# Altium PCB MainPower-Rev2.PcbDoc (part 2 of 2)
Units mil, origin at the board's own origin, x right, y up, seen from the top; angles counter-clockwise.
Board outline 7780 x 7780 mil, 4 copper layers (Top Layer, Internal Plane 1, Internal Plane 2, Bottom Layer); 128 components, 89 nets, 523 pads, 30 vias.
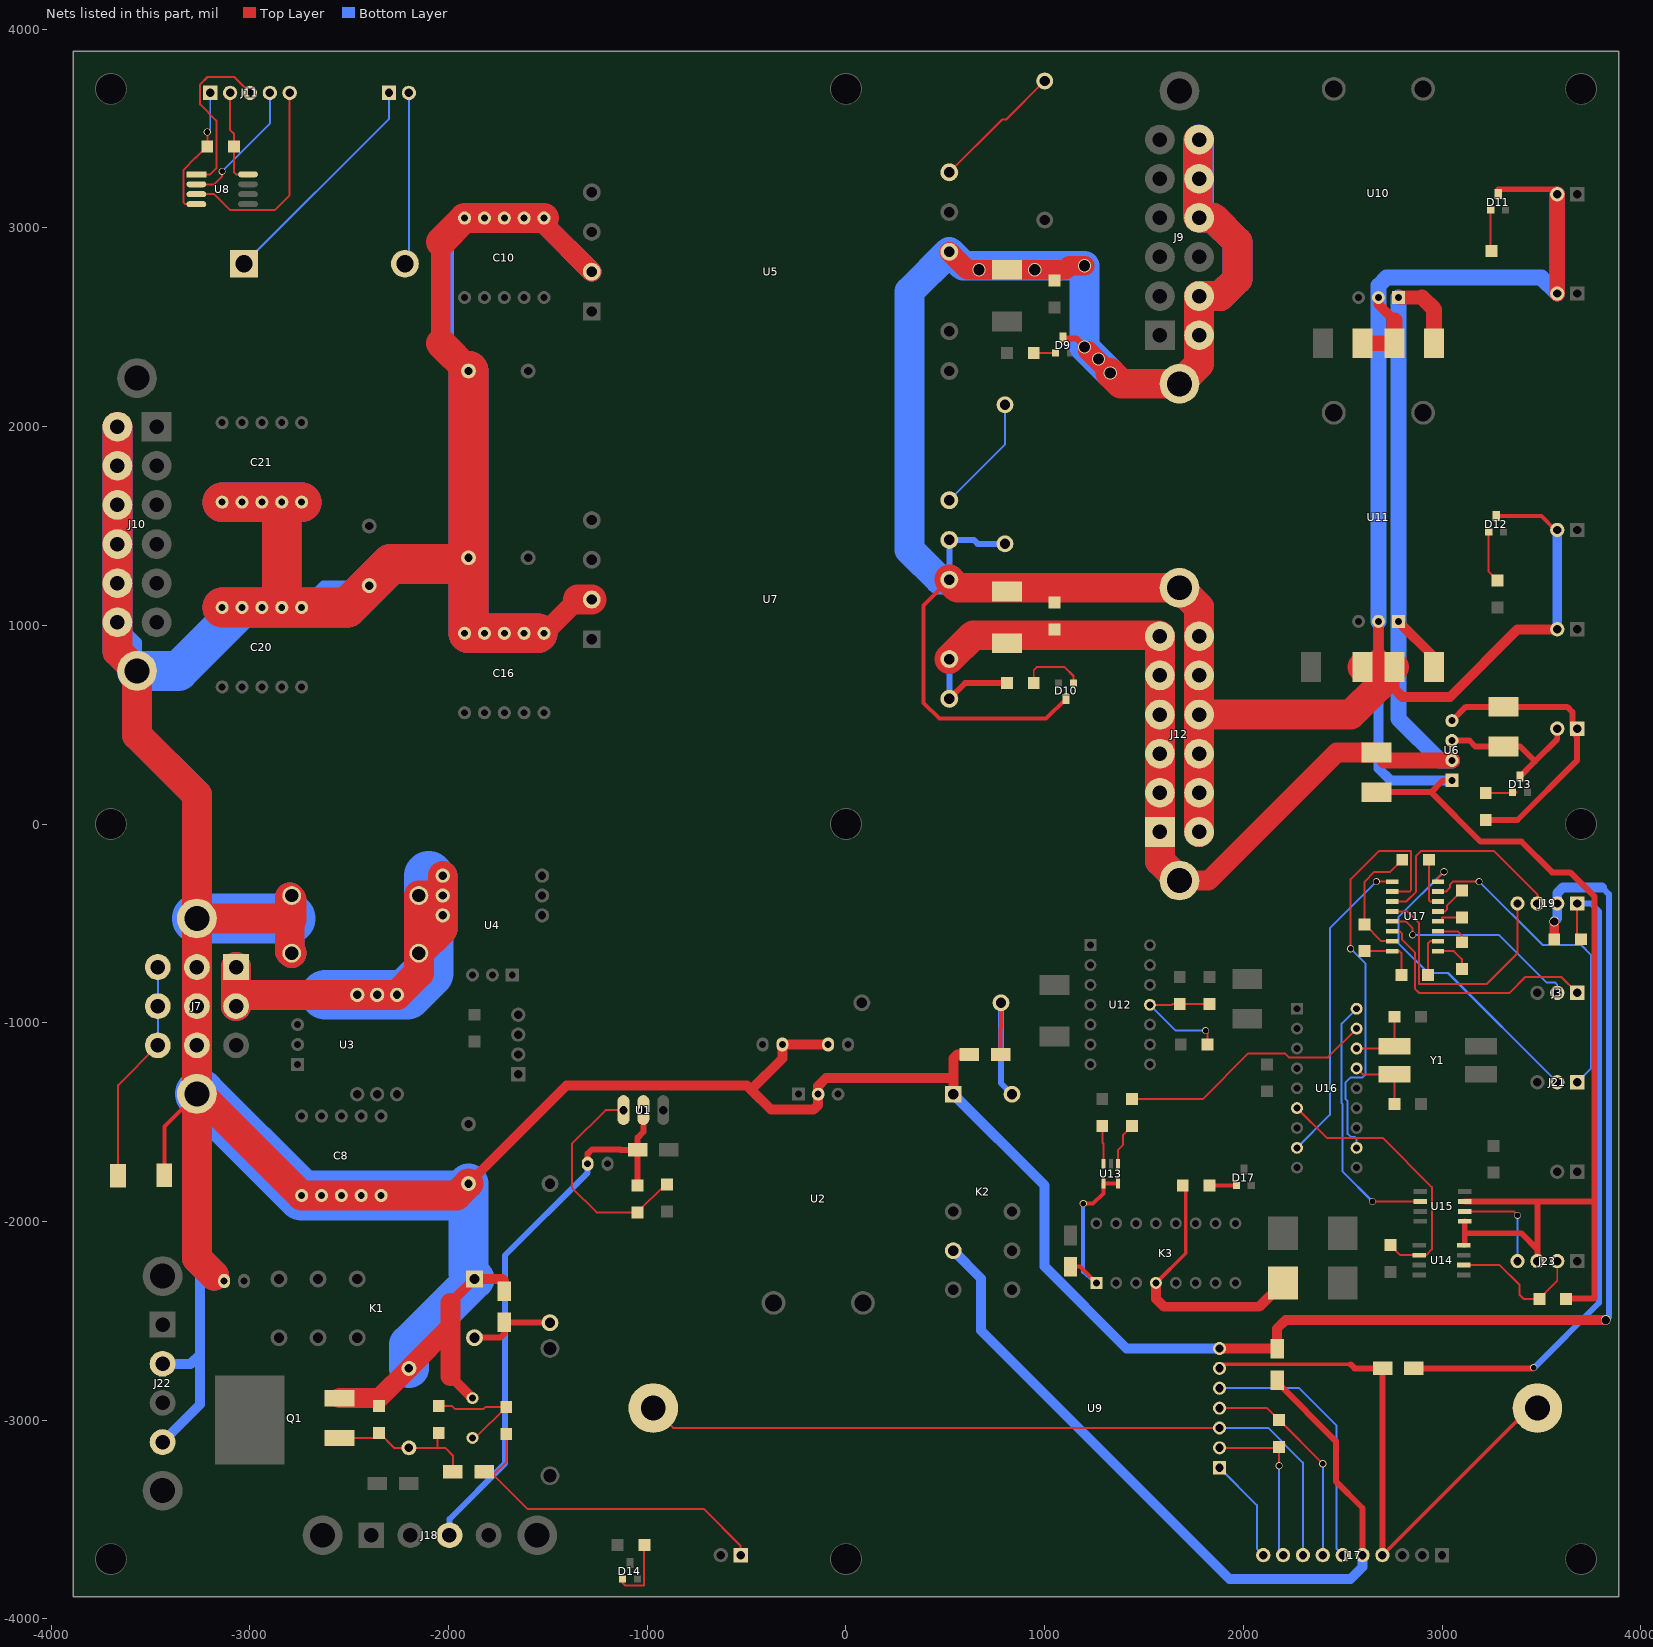
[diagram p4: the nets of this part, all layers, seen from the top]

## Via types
v1: diameter 36, hole 28, Top Layer to Bottom Layer, 15 vias
v2: diameter 50, hole 42, Top Layer to Bottom Layer, 9 vias
v3: diameter 66, hole 56, Top Layer to Bottom Layer, 6 vias

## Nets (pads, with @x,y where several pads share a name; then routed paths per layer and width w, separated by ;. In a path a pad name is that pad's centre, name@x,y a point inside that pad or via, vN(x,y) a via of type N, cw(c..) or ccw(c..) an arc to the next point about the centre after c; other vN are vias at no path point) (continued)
MVC12V+: C13.1 C17.1 C18.1 C22.1 C24.1 J12.0@1678.5,-284.5 J12.1 J12.2 J12.3 J12.4 J12.5 J12.6 R10.1 U6.2 U7.5 U7.6 U10.1 U11.1 | length 11136.6
  Top Layer w30: U7.5@520,630 600,710 R10.1@810,710
  Top Layer w50: U7.6@520,830 520,890 540,910 C18.1@810,910 937,910 1007,980 C17.1@1050,980 1545,980 J12.6@1580,945 ; C13.1@2670,360 C13.1@2710,320 ; U11.1@2780,1020 2960,840 C24.1@2960,790
  Top Layer w70: U10.1@2780,2650 2900,2650
  Top Layer w80: C13.1@2710,320 U6.2@3050,320 ; 2900,2650 2960,2590 C22.1@2960,2420
  Top Layer w100: J12.0@1678.5,-284.5 1825.5,-284.5 2470,360 C13.1@2670,360
  Top Layer w150: U7.6@520,830 640,950 J12.6@1575,950 ; J12.6@1580,945 1580,-186 J12.0@1678.5,-284.5
  Bottom Layer w30: U7.5@520,630 U7.6@520,830
  Bottom Layer w50: J12.1@1580,-40 J12.2@1580,157 J12.3@1580,354 J12.4@1580,551 J12.5@1580,748 J12.6@1580,945
  Bottom Layer w80: U10.1@2780,2650 U11.1@2780,1020 2780,530 2990,320 U6.2@3050,320
  Bottom Layer w150: J12.6@1580,945 1580,-186 J12.0@1678.5,-284.5
MVCGND: C11.2 C12.2 C13.2 C17.2 C18.2 C22.2 C23.2 C24.2 C25.2 D9.3 D10.3 D11.3 D12.3 J9.0@1678.5,2215.5 J9.7 J9.8 J9.10 J9.11 J9.12 J12.0@1678.5,1189.5 J12.7 J12.8 J12.9 J12.10 J12.11 J12.12 J13.2 J14.2 J15.2 J16.2 J23.3 R7.2 R19.2 U5.7 U6.1 U7.7 U7.8 U10.2 U11.2 U14.4 U15.5 U15.7 | length 29352.8
  Top Layer w20: U7.7@520,1230 390,1100 390,610 470,530 1007,530 D10.3@1107,630 ; D12.3@3273,1550 3500,1550 3570,1480 J15.2@3580,1480
  Top Layer w30: 995,2790 C11.2@1050,2735 ; D9.3@1093,2450 1093,2443 1161,2443 v3@1337,2257 ; C13.2@2670,160 2945,160 ; U6.1@3050,220 3005,220 2945,160 ; U14.4@3110,-2120 3114.41,-2120 U15.5@3114.41,-2000 ; 3114.41,-2060 3190,-2060 3400,-2060 3480,-2140 J23.3@3480,-2200 3480,-1900 ; U15.7@3114.41,-1900 3480,-1900 ; D11.3@3283,3170 3283,3195 3580,3195 J13.2@3580,3170 ; R19.2@3625,-2390 3627,-2388 3768,-2388 3768,-1900 ; 2945,160 3194,-89 3400,-89 3554,-243 3645,-243 3768,-366 3768,-1900 ; 3480,-1900 3768,-1900
  Top Layer w50: U7.7@520,1230 580,1170 C18.2@810,1170 995,1170 C17.2@1050,1115 ; C11.2@1050,2735 1125,2810 ; C25.2@2600,790 2680,870 ; U11.2@2680,1020 2680,870 ; U10.2@2680,2650 2680,2615 2760,2535 ; J16.2@3580,980 3380,980 3040,640 2800,640 2760,680 C24.2@2760,790 2680,870
  Top Layer w80: C23.2@2600,2420 C22.2@2760,2420 2760,2535 ; J14.2@3580,2670 J13.2@3580,3170
  Top Layer w100: U5.7@520,2880 610,2790 C12.2@810,2790 995,2790 1105,2790 1125,2810 v3(1200,2810) ; v3@1218,2382 v3(1330,2270)
  Top Layer w150: U7.7@520,1230 560.5,1189.5 J12.0@1678.5,1189.5 1777,1091 J12.7@1777,-40 ; v3(1330,2270) 1384.5,2215.5 J9.0@1678.5,2215.5 1777,2314 J9.7@1777,2460 ; J9.12@1770,3440 J9.10@1770,3058 ; J12.10@1777,551 2541,551 2680,690 2680,790 ; C25.2@2600,790 C24.2@2760,790 ; J9.10@1770,3058 J9.10@1777,3051 ; J9.10@1770,3058 J9.10@1777,3051 ; J9.7@1777,2460 J9.8@1777,2657 ; J9.7@1777,2460 J9.8@1777,2657 ; J9.8@1777,2657 1884,2657 1970,2743 1970,2930 1849,3051 J9.10@1777,3051
  Bottom Layer w30: U7.7@520,1230 U7.8@520,1430 643,1430 663,1410 R7.2@800,1410
  Bottom Layer w50: J12.7@1777,-40 J12.8@1777,157 J12.9@1777,354 J12.10@1777,551 J12.11@1777,748 J12.12@1777,945 ; U11.2@2680,1020 2680,280 2740,220 U6.1@3050,220 ; J16.2@3580,980 J15.2@3580,1480
  Bottom Layer w80: U11.2@2680,1020 U10.2@2680,2650 2680,2710 2720,2750 3500,2750 J14.2@3580,2670 J13.2@3580,3170
  Bottom Layer w150: U7.7@520,1230 470,1230 320,1380 320,2680 U5.7@520,2880 590,2810 v3(1200,2810) v3(1200,2400) v3(1330,2270) ; J12.0@1678.5,1189.5 1777,1091 1777,930 J12.7@1777,-40 ; J9.7@1777,2460 J9.8@1777,2657 1884,2657 1970,2743 1970,2930 1849,3051 J9.10@1777,3051 J9.11@1777,3248 J9.12@1777,3445
  other v3: 1270,2340 670,2790 950,2790
NetB1_1: B1.1 J20.1 | length 1162.4
  Bottom Layer w10: B1.1@-3030,2820 -2300,3550 J20.1@-2300,3680
NetB1_2: B1.2 J20.2 | length 868.3
  Bottom Layer w10: B1.2@-2220,2820 -2200,2840 J20.2@-2200,3680
NetC5_1: C5.1 R3.2 R4.1 | length 585.1
  Top Layer w10: R4.1@-2050,-2930 -1982,-2930 -1966.39,-2945.61 -1825.61,-2945.61 -1815,-2935 -1795,-2935 R3.2@-1710,-2935 -1865,-3090 C5.1@-1880,-3090
NetC26_2: C26.2 R15.2 R16.1 U12.11 | length 710.1
  Top Layer w10: U12.11@1530,-910 1640,-910 1645,-905 C26.2@1680,-905 R15.2@1830,-905 ; v1(1810,-1040) 1820,-1050 R16.1@1820,-1110
  Bottom Layer w10: U12.11@1530,-910 1660,-1040 v1(1810,-1040)
NetC30_1: C30.1 U16.16 Y1.4 | length 350
  Top Layer w10: U16.16@2570,-1130 2721,-1130 2721,-1118.27 Y1.4@2760,-1118.27 C30.1@2760,-970
NetC31_1: C31.1 U16.15 Y1.1 | length 352.4
  Top Layer w10: U16.15@2570,-1230 2600,-1260 Y1.1@2760,-1260 C31.1@2760,-1410
NetC33_1: C33.1 C34.2 U17.16 | length 299.1
  Top Layer w10: C33.1@2610,-640 U17.16@2749.69,-640 2785,-640 2795,-650 C34.2@2795,-760
NetC33_2: C33.2 C36.1 U17.15 | length 624.9
  Top Layer w10: U17.15@2749.69,-590 2695,-590 C33.2@2610,-505 2610,-291 2660,-241 2739,-241 C36.1@2800,-180
NetC34_1: C34.1 U17.2 | length 214.1
  Top Layer w10: C34.1@2930,-760 2930,-600 2940,-590 U17.2@2980,-590
NetC35_1: C35.1 U17.1 | length 186.6
  Top Layer w10: U17.1@2980,-640 3060,-640 3100,-680 C35.1@3100,-730
NetC35_2: C35.2 U17.3 | length 163.3
  Top Layer w10: U17.3@2980,-540 3080,-540 3100,-560 C35.2@3100,-595
NetC36_2: C36.2 U17.6 | length 252.1
  Top Layer w10: C36.2@2935,-180 2935,-213 2934.29,-213.71 2934.29,-383.29 2941,-390 U17.6@2980,-390
NetC37_1: C37.1 U17.4 | length 140
  Top Layer w10: U17.4@2980,-490 2999,-490 2999,-470 C37.1@3100,-470
NetC37_2: C37.2 U17.5 | length 175.8
  Top Layer w10: U17.5@2980,-440 3016,-440 3026,-430 3026,-409 C37.2@3100,-335
NetC38_1: C38.1 J11.2 U8.8 | length 482.4
  Top Layer w10: J11.2@-3100,3680 -3100,3493 -3080,3473 C38.1@-3080,3410 -3080,3280 -3070,3270 U8.8@-3010,3270
NetC38_2: C38.2 J11.1 U8.4 | length 676.7
  Top Layer w10: U8.4@-3270,3120 -3325,3120 -3335.61,3130.61 -3335.61,3291.39 -3272,3355 -3270,3355 C38.2@-3215,3410 v1(-3215,3483)
  Bottom Layer w10: v1(-3215,3483) -3200,3498 J11.1@-3200,3680
NetD1_2: D1.2 K1.8 R1.1 | length 444.8
  Top Layer w10: -1720,-2565.28 -1720,-2510 D1.2@-1720,-2508.74
  Top Layer w30: K1.8@-1870,-2585.28 -1740,-2585.28 -1720,-2565.28 ; D1.2@-1720,-2510 R1.1@-1490,-2510
NetD3_2: D3.2 K2.8 R2.1 | length 743.4
  Top Layer w10: 778.74,-1030.26 780,-1029
  Top Layer w20: D3.2@778.74,-1160 778.74,-1030.26 ; 780,-1029 R2.1@780,-900
  Bottom Layer w30: R2.1@780,-900 780,-1304.72 K2.8@835.28,-1360
NetD5_2: D5.2 J4.1 R3.1 | length 1725.4
  Top Layer w10: D5.2@-1821.26,-3260 -1791,-3260 D5.2@-1774.5,-3276.5 ; R3.1@-1710,-3070 -1710,-3212 D5.2@-1774.5,-3276.5 ; J4.1@-530,-3680 -530,-3634 -717,-3447 -1604,-3447 D5.2@-1774.5,-3276.5
NetD9_2: D9.2 R8.2 | length 110
  Top Layer w10: R8.2@945,2370 D9.2@1055,2370
NetD10_2: D10.2 R10.2 | length 324.9
  Top Layer w10: R10.2@945,710 945,775 960,790 1100,790 1145,745 D10.2@1145,710
NetD11_2: D11.2 R12.2 | length 212.1
  Top Layer w10: R12.2@3250,2885 3245,2890 D11.2@3245,3090 D11.2@3250,3090
NetD12_2: D12.2 R9.2 | length 263.6
  Top Layer w10: D12.2@3235,1470 3235,1270 R9.2@3280,1225
NetD13_2: D13.2 R14.2 | length 179.1
  Top Layer w10: R14.2@3220,155 3355,155 3371,155 3376,160 D13.2@3355,160
NetD14_2: D14.2 R11.2 | length 337.8
  Top Layer w10: D14.2@-1125,-3800 -1125,-3820 -1112,-3833 -1016,-3833 -1016,-3631 R11.2@-1015,-3630
NetD15_1: D15.1 K3.1 U13.1 U13.2 | length 841.4
  Top Layer w10: D15.1@1130,-2228.74 D15.1@1130,-2228
  Top Layer w20: D15.1@1130,-2228 1178,-2228 K3.1@1260,-2310 ; v1(1194,-1911) 1244,-1911 1295,-1860 U13.2@1295,-1810 U13.1@1370,-1810
  Bottom Layer w20: v1(1194,-1911) 1194,-2254 K3.1@1260,-2310
NetD17_2: D17.2 R22.1 | length 135
  Top Layer w20: R22.1@1830,-1820 D17.2@1965,-1820
NetD19_1: D19.1 J17.4 U9.00 U9.6 | length 2864.9
  Top Layer w18: U9.6@1880,-2740 1900,-2720 2540,-2720 ; J17.4@2700,-3680 3440,-2940 U9.00@3480,-2940 ; D19.1@2700,-2741.26 D19.1@2701.26,-2740
  Top Layer w30: 2540,-2720 2560,-2740 D19.1@2701.26,-2740 ; J17.4@2700,-3680 D19.1@2700,-2741.26
NetF1_1: F1.1 K3.4 R22.2 | length 1399.6
  Top Layer w10: F1.1@2200,-2365 F1.1@2200,-2310
  Top Layer w18: K3.4@1560,-2310 1710,-2160 1710,-1835 R22.2@1695,-1820
  Top Layer w50: K3.4@1560,-2310 1560,-2390 1600,-2430 2080,-2430 F1.1@2200,-2310
NetJ3_1: J3.1 U17.14 | length 1250.4
  Top Layer w10: U17.14@2749.69,-540 2788,-540 2798,-550 2798,-581 2863,-646 2863,-829 2884,-850 3340,-850 3420,-770 3600,-770 J3.1@3680,-850
NetJ3_2: J3.2 U17.13 | length 1023.4
  Top Layer w10: U17.13@2749.69,-490 2818,-490 2852,-524 v1(2852,-558)
  Bottom Layer w10: v1(2852,-558) 3286,-558 3527,-799 3570,-799 3580,-809 J3.2@3580,-850
NetJ5_1: 
NetJ5_2: 
NetJ11_3: J11.3 U8.1 | length 869
  Top Layer w10: U8.1@-3270,3270 -3200,3270 -3169.59,3300.41 -3169.59,3540.59 -3251.34,3622.34 -3251.34,3722.52 -3213.86,3760 -3080,3760 J11.3@-3000,3680
NetJ11_4: J11.4 U8.2 | length 666
  Top Layer w10: U8.2@-3270,3220 -3180,3220 -3140,3260 v1(-3140,3285)
  Bottom Layer w10: v1(-3140,3285) -2900,3525 J11.4@-2900,3680
NetJ11_5: J11.5 U8.3 | length 1050
  Top Layer w10: U8.3@-3270,3170 -3180,3170 -3099.75,3089.75 -2874.25,3089.75 -2800,3164 J11.5@-2800,3680
NetJ17_6: J17.6 U9.5 | length 1331.7
  Bottom Layer w10: U9.5@1880,-2840 2281,-2840 2469,-3028 2469,-3649 J17.6@2500,-3680
NetJ17_7: J17.7 R13.1 U9.4 | length 1096
  Top Layer w10: U9.4@1880,-2940 2120,-2940 R13.1@2180,-3000 v1(2400,-3220)
  Bottom Layer w10: J17.7@2400,-3680 v1(2400,-3220)
NetJ17_8: J17.8 U9.0 U9.3 | length 3848.9
  Top Layer w10: U9.0@-970,-2940 -870,-3040 U9.3@1880,-3040
  Bottom Layer w10: U9.3@1880,-3040 2125,-3040 2300,-3215 J17.8@2300,-3680
NetJ17_9: J17.9 R13.2 U9.2 | length 855.4
  Top Layer w10: U9.2@1880,-3140 2175,-3140 R13.2@2180,-3135 v1(2180,-3230)
  Bottom Layer w10: v1(2180,-3230) 2180,-3660 J17.9@2200,-3680
NetJ17_10: J17.10 U9.1 | length 531.1
  Bottom Layer w10: U9.1@1880,-3240 2068,-3428 2068,-3648 J17.10@2100,-3680
NetJ21_1: J21.1 U17.7 | length 1623.2
  Top Layer w10: U17.7@2980,-340 3020,-340 3040,-320 3040,-305 3055,-290 v1(3187,-290)
  Bottom Layer w10: v1(3187,-290) 3506,-609 3700,-609 3751,-660 3751,-1229 J21.1@3680,-1300
NetJ21_2: J21.2 U17.8 | length 1607.6
  Top Layer w10: U17.8@2980,-290 2980,-270 v1(3010,-240)
  Bottom Layer w10: v1(3010,-240) 2780,-470 2780,-600 2930,-750 3030,-750 J21.2@3580,-1300
NetJ21_3: 
NetR6_1: R6.1 U5.9 | length 670.5
  Top Layer w10: U5.9@520,3280 786,3546 806,3546 R6.1@1000,3740
NetR7_1: R7.1 U7.9 | length 596
  Bottom Layer w10: U7.9@520,1630 800,1910 R7.1@800,2110
NetR17_1: R17.1 U14.6 U16.6 | length 1398.6
  Top Layer w10: U16.6@2270,-1430 2420,-1580 2701,-1580 2948.99,-1827.99 2948.99,-2141.01 2920,-2170 U14.6@2885.59,-2170 2790,-2170 R17.1@2740,-2120
NetR20_1: R20.1 U13.5 | length 219
  Top Layer w10: U13.5@1370,-1710 1370,-1640 1395,-1615 1395,-1565 R20.1@1440,-1520
NetR20_2: R20.2 U16.17 | length 1294
  Top Layer w10: R20.2@1440,-1385 1795,-1385 2025.51,-1154.49 2208.49,-1154.49 2229,-1175 2425,-1175 U16.17@2570,-1030
NetR21_1: R21.1 U13.3 | length 192.1
  Top Layer w10: R21.1@1290,-1520 1290,-1604 1295,-1609 U13.3@1295,-1710
NetR25_2: R25.2 R26.2 U1.1 | length 1140.2
  Top Layer w10: U1.1@-1120,-1440 -1210,-1440 -1380,-1610 -1380,-1830 -1255,-1955 R25.2@-1050,-1955 -910,-1815 R26.2@-900,-1815
NetU15_2: U15.2 U16.18 | length 1305.3
  Top Layer w10: v1(2650,-1900) U15.2@2890,-1900
  Bottom Layer w10: U16.18@2570,-930 2495,-1005 2495,-1405 2500,-1410 2500,-1703 2500,-1750 v1(2650,-1900)
PARO9V+: C14.1 J1.1 R14.1 U6.4 | length 1526
  Top Layer w30: U6.4@3050,520 3120,590 C14.1@3310,590 3630,590 3657,563 3657,480 3657,461 3659,459 3680,438 ; R14.1@3220,20 3380,20 3680,320 3680,438 ; J1.1@3680,480 3680,438
PARO9VGND: C14.2 D13.3 J1.2 U6.3 | length 779
  Top Layer w30: U6.3@3050,420 3138,420 3168,390 C14.2@3310,390 3393,390 3468,315 ; D13.3@3393,240 3468,315 ; J1.2@3580,480 3580,427 3468,315
PICRX: U16.8 U17.9 | length 1585.4
  Top Layer w10: v1(2670,-290) U17.9@2749.69,-290
  Bottom Layer w10: U16.8@2270,-1630 2436,-1464 2436,-524 v1(2670,-290)
PICTX: U16.11 U17.10 | length 2154
  Top Layer w10: v1(2540,-628) 2540,-278 2683,-135 2845,-135 2845,-332 2837,-340 U17.10@2749.69,-340
  Bottom Layer w10: v1(2540,-628) 2615,-703 2615,-1260 2600,-1275 2540,-1275 2515,-1300 2515,-1385 2525,-1395 2525,-1560 2540,-1575 2560,-1575 2570,-1585 U16.11@2570,-1630
PTT-TTL-SER-RX: J19.4 U17.12 | length 1275.8
  Top Layer w10: U17.12@2749.69,-440 2825,-440 2885,-500 2885,-806 3224,-806 3380,-650 J19.4@3380,-400
PTT-TTL-SER-TX: J19.3 U17.11 | length 1078.1
  Top Layer w10: U17.11@2749.69,-390 2820,-390 2870,-340 2870,-160 2895,-135 3261,-135 3480,-354 J19.3@3480,-400
Q1G: D5.1 D6.2 Q1.1 R4.2 R5.2 | length 800.4
  Top Layer w10: Q1.1@-2550,-3090 -2350,-3090 R5.2@-2350,-3065 -2275,-3140 D6.2@-2200,-3140 -2125,-3140 -2018,-3140 -1978,-3180 -1978,-3260 D5.1@-1978.74,-3260 ; -2055,-3140 R4.2@-2055,-3065
RAWBUS+: D7.2 D8.2 J7.1 J7.2 U3.4 U3.5 U3.6 U4.4 U4.5 U4.6 | length 6900.1
  Top Layer w150: J7.2@-3070,-917 J7.1@-3070,-720 ; -3070,-850 -3060,-860 U3.4@-2260,-860 -2150,-750 D7.2@-2150,-650 ; U4.5@-2030,-360 D8.2@-2150,-360 D7.2@-2150,-650 ; U4.4@-2030,-260 -2030,-530 D7.2@-2150,-650
  Bottom Layer w50: J7.1@-3070,-720 J7.2@-3070,-917 -3013,-860 U3.6@-2460,-860 U3.5@-2360,-860 U3.4@-2260,-860 -2260,-760 D7.2@-2150,-650 -2030,-530 U4.6@-2030,-460 U4.5@-2030,-360 ; D8.2@-2150,-360 U4.5@-2030,-360 ; U4.4@-2030,-260 U4.5@-2030,-360
  Bottom Layer w150: J7.2@-3070,-917 J7.1@-3070,-720 ; J7.2@-3060,-860 U3.4@-2260,-860 -2150,-750 ; D8.2@-2150,-360 D7.2@-2150,-650 -2030,-530 U4.4@-2030,-260
  Bottom Layer w250: -2620,-860 -2210,-860 -2100,-750 -2100,-260
RAWBUS-: C1.2 C2.2 C4.2 C5.2 C6.2 C7.2 C8.2 C9.2 C10.2 C15.2 C16.2 C19.2 C20.2 C21.2 C32.2 D1.1 D3.1 D4.1 D6.1 D7.1 D8.1 J7.0 J7.4 J7.5 J7.6 J10.0@-3568.5,770.5 J10.7 J10.8 J10.9 J10.10 J10.11 J10.12 J19.2 J22.2 J22.4 K1.1 K2.1 Q1.3 R5.1 U2.2 U5.2 U7.2 U9.7 | length 54894
  Top Layer w20: C6.2@-3430.83,-1768.7 -3430.83,-1522.33 J7.0@-3267,-1358.5 J7.0@-3267,-1367
  Top Layer w50: R5.1@-2350,-2930 -2350,-2890 D6.1@-2200,-2740 ; -1990,-2780 C5.2@-1880,-2890 -1920,-2850 ; -1990,-2410 K1.1@-1870,-2290 -1730,-2290 -1720,-2300 D1.1@-1720,-2351.26 ; C7.2@-1900,-1810 -1406,-1316 -499,-1316 -477.5,-1337.5 ; C16.2@-1520,960 -1350,1130 U7.2@-1280,1130 ; C4.2@-90,-1110 C2.2@-320,-1110 -320,-1180 -477.5,-1337.5 ; K2.1@540,-1360 540,-1278 ; D3.1@621.26,-1160 560,-1160 540,-1180 540,-1278 ; U9.7@1880,-2640 D4.1@2170,-2640 ; D4.1@2170,-2641.26 D4.1@2170,-2640 ; C32.2@3565,-580 v2(3565,-491) ; v2(3824,-2497) 2213,-2497 2170,-2540 D4.1@2170,-2640 ; -477.5,-1337.5 -377.37,-1437.63 -162.63,-1437.63 -140,-1415 U2.2@-140,-1360 -140,-1318 -100,-1278 540,-1278
  Top Layer w100: Q1.3@-2550,-2890 -2350,-2890 D6.1@-2200,-2740 ; D6.1@-2201,-2741 -1990,-2530 ; -2040,2420 -2040,2930 ; -1990,-2780 -1990,-2410 ; C16.2@-1520,960 -1350,1130 ; C10.2@-1520,3050 -1520,3020 U5.2@-1280,2780
  Top Layer w150: J10.7@-3667,2000 -3667,869 J10.0@-3568.5,770.5 -3568.5,448.5 -3267,147 J7.0@-3267,-1358.5 ; J7.0@-3267,-475.5 -2794.5,-475.5 -2790,-480 -2790,-380 -2800,-370 -2800,-640 D7.1@-2790,-650 ; -3180,-2272.52 -3267,-2185.52 J7.0@-3267,-1358.5 ; -2040,2420 C9.2@-1900,2280 ; -2040,2930 C10.2@-1920,3050 C10.2@-1520,3050 ; C7.2@-1900,-1810 -1960,-1870 C8.2@-2740,-1870 -3251.5,-1358.5 J7.0@-3267,-1358.5 ; -1350,1130 U7.2@-1280,1130
  Top Layer w200: C20.2@-3140,1090 -2510,1090 -2291.23,1308.77 -1931.23,1308.77 C15.2@-1900,1340 ; C21.2@-3140,1620 C21.2@-2740,1620 ; C20.2@-2840,1090 C21.2@-2840,1620 ; C9.2@-1900,2280 C15.2@-1900,1340 ; C16.2@-1551.13,960 -1900,960 C15.2@-1900,1340
  Bottom Layer w30: 3805.62,-318.72 3840,-353.11 3840,-2480 3840,-2481 v2(3824,-2497)
  Bottom Layer w50: J10.7@-3667,2000 J10.8@-3667,1803 J10.9@-3667,1606 J10.10@-3667,1409 J10.11@-3667,1212 J10.12@-3667,1015 -3568.5,916.5 J10.0@-3568.5,770.5 ; J22.4@-3440,-3111 -3251,-2922 -3251,-2723 -3251,-2540 -3251,-1374.5 J7.0@-3267,-1358.5 J7.6@-3267,-1114 J7.5@-3267,-917 J7.4@-3267,-720 J7.0@-3267,-475.5 ; J22.2@-3440,-2717 -3298,-2717 -3251,-2670 ; J7.0@-3270,-1370 J7.0@-3240,-1370 ; J7.0@-3260,-1370 -2760,-1870 C8.2@-2740,-1870 C8.2@-2640,-1870 C8.2@-2540,-1870 C8.2@-2440,-1870 C8.2@-2340,-1870 -2350,-1880 -1970,-1880 C7.2@-1900,-1810 -1900,-1876 -1900,-2290 K1.1@-1870,-2290 ; -3251,-2260 -3211,-2300 C1.2@-3130,-2300 ; C21.2@-3140,1620 C21.2@-3040,1620 C21.2@-2940,1620 C21.2@-2840,1620 ; D7.1@-2790,-650 -2790,-591 -2905.5,-475.5 ; D8.1@-2790,-360 -2905.5,-475.5 ; C21.2@-2740,1620 C21.2@-2840,1620 ; C16.2@-1520,960 C16.2@-1620,960 C16.2@-1720,960 C16.2@-1820,960 C16.2@-1920,960 -1920,1150 -1900,1170 C15.2@-1900,1340 ; U5.2@-1280,2780 -1405,2905 -1405,2935 C10.2@-1520,3050 C10.2@-1620,3050 C10.2@-1720,3050 C10.2@-1820,3050 C10.2@-1920,3050 -1998,2972 -1998,2378 C9.2@-1900,2280 C15.2@-1900,1340 ; K2.1@540,-1360 1000,-1820 1000,-2228 1412,-2640 U9.7@1880,-2640 ; v2(3565,-491) 3580,-476 J19.2@3580,-400 3580,-348 3609.28,-318.72 3805.62,-318.72 ; J10.0@-3568.5,770.5 -3568.5,438.5 -3267,137 J7.0@-3267,-475.5 ; J10.0@-3568.5,770.5 -3459.5,770.5 C20.2@-3140,1090 C20.2@-3040,1090 C20.2@-2940,1090 C20.2@-2840,1090 ; J7.0@-3267,-475.5 -2905.5,-475.5 ; C20.2@-2840,1090 C21.2@-2840,1620 ; C20.2@-2840,1090 C20.2@-2740,1090 -2630,1200 C19.2@-2400,1200 -2260,1340 C15.2@-1900,1340
  Bottom Layer w100: C9.2@-1900,2280 -2040,2420 -2040,2930 C10.2@-1920,3050 C10.2@-1520,3050 ; C10.2@-1520,3020 U5.2@-1280,2780
  Bottom Layer w150: J10.7@-3667,2000 -3667,869 J10.0@-3568.5,770.5 -3568.5,448.5 -3267,147 J7.0@-3267,-1358.5 -3267,-2185.52 -3180,-2272.52 ; D8.1@-2800,-370 -2800,-640 D7.1@-2790,-650 ; -1960,-1870 C7.2@-1900,-1810
  Bottom Layer w200: J10.0@-3568.5,770.5 -3359.5,770.5 C20.2@-3040,1090 ; C20.2@-3140,1090 -2510,1090 -2291.23,1308.77 -1931.23,1308.77 ; C21.2@-3140,1620 C21.2@-2740,1620 ; C20.2@-2840,1090 C21.2@-2840,1620 ; D6.1@-2200,-2740 -2200,-2620 K1.1@-1870,-2290 -1900,-2260 C7.2@-1900,-1810 ; C9.2@-1900,2280 C15.2@-1900,1340 -1900,960 C16.2@-1551.13,960
  Bottom Layer w250: J7.0@-3267,-475.5 -2794.5,-475.5 ; J7.0@-3251.5,-1358.5 C8.2@-2740,-1870 -1960,-1870
SHIELD: C6.1 J7.7 J7.8 J7.9 | length 1132.6
  Top Layer w10: C6.1@-3664.09,-1769.68 -3664.09,-1314.09 J7.9@-3464,-1114
  Bottom Layer w10: J7.9@-3464,-1114 J7.8@-3464,-917 J7.7@-3464,-720
SW10VDC: D4.2 J17.5 K2.3 | length 4042.6
  Top Layer w30: D4.2@2170,-2798.74 2170,-2810 2466,-3106 2466,-3309 2600,-3443 J17.5@2600,-3680
  Bottom Layer w50: K2.3@540,-2147.4 680,-2287.4 680,-2550 1930,-3800 2540,-3800 2600,-3740 J17.5@2600,-3680
V+PTT: C32.1 D19.2 J19.1 | length 3372.8
  Top Layer w10: J19.1@3680,-400 3680,-560 C32.1@3700,-580
  Top Layer w30: D19.2@2858.74,-2740 3457,-2740 v1(3461,-2736)
  Bottom Layer w10: J19.1@3680,-420 J19.1@3680,-400
  Bottom Layer w30: v1(3461,-2736) 3464,-2736 3790,-2410 3790,-440 3750,-400 J19.1@3680,-400
V+USBL: C3.1 D18.1 J18.3 R25.1 U1.2 | length 2862
  Top Layer w30: C3.1@-1300,-1710 -1300,-1659 -1279.59,-1638.59 -1135.41,-1638.59 -1134,-1640 D18.1@-1048.74,-1640 ; R25.1@-1050,-1820 -1048.74,-1818.74 D18.1@-1048.74,-1640 ; U1.2@-1020,-1440 -1020,-1550 -1048.74,-1578.74 D18.1@-1048.74,-1640
  Bottom Layer w30: J18.3@-1996,-3580 -1996,-3499 -1717,-3220 -1717,-2172 -1300,-1755 C3.1@-1300,-1710
WDC: J23.2 R19.1 U14.2 | length 707
  Top Layer w10: U14.2@3110,-2220 3290,-2220 3390,-2320 3390,-2370 3410,-2390 R19.1@3490,-2390 3580,-2300 J23.2@3580,-2200
WDSTATUS: J23.4 U15.6 | length 503.9
  Top Layer w10: U15.6@3114.41,-1950 3360,-1950 v1(3380,-1970)
  Bottom Layer w10: J23.4@3380,-2200 v1(3380,-1970)
pads on no net: D9.1 D10.1 D11.1 D12.1 D13.1 D14.1 D17.1 F2.1 F2.2 J9.0@1678.5,3689.5 J18.0 J22.0 K1.5 K1.6 K1.7 K2.5 K2.6 K2.7 K3.2 K3.3 K3.5 K3.6 K3.7 K3.10 K3.11 K3.12 K3.14 K3.15 U2.0 U5.3 U5.4 U7.3 U7.4 U8.5 U8.6 U8.7 U10.0 U11.0 U12.1 U12.4 U12.5 U12.6 U12.7 U12.8 U12.10 U12.12 U12.13 U12.14 U16.2 U16.3 U16.7 U16.9 U16.10 U16.12 U16.13 Y1.2 Y1.3

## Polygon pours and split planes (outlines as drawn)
no net on Internal Plane 1 (split plane): -3869.99,-3869.99 -3869.99,3869.99 3869.99,3869.99 3869.99,-3869.99
no net on Internal Plane 2 (split plane): -3869.99,-3869.99 -3869.99,3869.99 3869.99,3869.99 3869.99,-3869.99

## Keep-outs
Keep-Out Layer:
  circle w10: c-3700,-3700 r200
  circle w10: c0,-3700 r200
  circle w10: c3700,-3700 r200
  circle w10: c3700,0 r200
  circle w10: c0,0 r200
  circle w10: c-3700,0 r200
  circle w10: c-3700,3700 r200
  circle w10: c0,3700 r200
  circle w10: c3700,3700 r200
  lines w10: -3880,-3880 -3880,3880 3880,3880 3880,-3880 -3880,-3880
  text ".GKO" at 9930,-6040 h90

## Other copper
Top Layer:
  text ".GTL" at 9930,-6040 h90
Bottom Layer:
  text "94V-0" at 627.07,-3841.21 h50
  text ".GBL" at 9930,-6040 h90

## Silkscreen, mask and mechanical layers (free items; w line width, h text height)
Top Overlay:
  lines w10: -1267,-114 -1235,-116 -1204,-134 -1103,-225 -1090,-221 -1083,-222 -969,-309 ; -1212,-132 -1109,-229 ; -1104,-232 -1089,-228 -974,-316 ; -987,-332 -941,-305 -882,-251 -879,-244 -879,-234 -881,-231 -887,-230 -894,-230 ; -956,-330 -909,-367 ; -952,-323 -904,-361 -752,-223 -743,-219 -729,-224 -650,-138 -647,-143 -618,-117 -598,-113 ; -880,-245 -880,-237 -882,-233 -887,-231 -894,-230 ; -746,-227 -731,-232 ; -724,-228 -659,-155 ; -656,-158 -650,-149 ; -894,-230 -968,-268 -976,-270 -983,-268 -987,-261 -986,-255 -982,-247 -971,-239 -876,-174 -868,-165 -865,-158 -867,-153 -869,-149 -873,-147 -880,-147 -890,-150 -1018,-220 -1028,-221 -1036,-216 -1041,-212 -1044,-205 -1043,-199 -1039,-191 -1017,-166 -989,-139 -950,-105 -907,-77 -868,-59 -819,-51 -862,-90 -845,-90 -816,-85 -811,-81 -828,-91 -844,-96 -860,-102 -883,-107 -918,-107 -925,-118 -938,-126 -953,-133 -971,-143 -993,-173 -1011,-188 -1022,-203 -1018,-207 -988,-197 -940,-169 -904,-149 -880,-143 -874,-145 -870,-156 -881,-172 -949,-219 -987,-251 -988,-263 -984,-268 -961,-264 -944,-253 -901,-233 -894,-230 ; -903,-372 -744,-227 -903,-372
  text "M  B  A  R  I" at -1270,-60 h55
  text "Copyright 2004 MBARI" at -1240,-500 h45
  text "1002131-MVCPowerR2" at -1235,-583.32 h45
  text "2004-JAN-02" at -1235,-663.32 h45
  text "Made in U.S.A." at -1235,-733.32 h45
  text "ADUM" at 2980,-1850 h45 r270
  text "ADUM" at 3020,-2270 h45 r90
  text "Spare" at 2420,-2450 h45
  text ".GTO" at 9930,-6040 h90
Bottom Overlay:
  text ".GBO" at 9940,-6040 h90
Top Solder:
  text ".GTS" at 9930,-6040 h90
Bottom Solder:
  text ".GBS" at 9930,-6040 h90
Drill Guide:
  text ".GG1" at 9950,-6040 h90
Mechanical 4:
  the board outline again, w10
Mechanical 16:
  lines w5: -6300,-3700 -6100,-3700 ; -6300,-1300 -6100,-1300 ; -6300,1100 -6100,1100 ; -6300,3500 -6100,3500 ; -3900.79,4266.58 -3900.79,4466.58 ; -3900,-6300 -3900,-6100 ; -1500.79,4266.58 -1500.79,4466.58 ; -1500,-6300 -1500,-6100 ; 899.21,4266.58 899.21,4466.58 ; 900,-6300 900,-6100 ; 3299.21,4266.58 3299.21,4466.58 ; 3300,-6300 3300,-6100 ; 4390,-5500 10290,-5500 ; 5699.21,4266.58 5699.21,4466.58 ; 5700,-6300 5700,-6100 ; 5790,-5800 10290,-5800 ; 5790,-5200 7290,-5200 ; 7290,-6100 7290,-5500 7290,-4900 ; 8099.21,4266.58 8099.21,4466.58 ; 8100,-6300 8100,-6100 ; 9390,-6100 9390,-5500 ; 10290,-4900 7290,-4900 ; 10290,-3700 10490,-3700 ; 10290,-1300 10490,-1300 ; 10290,1100 10490,1100 ; 10290,3500 10490,3500 ; 10290,4280 10290,-6100 -6100,-6100 -6100,4280 10295,4280 ; 10500,-6100 10500,-6300 ; 5790,-4900 5790,-6100 4390,-6100 4390,-4900 5790,-4900 ; 5790,-4900 7290,-4900 ; 10500,-6300 10500,4480 -6300,4480 -6300,-6300 10500,-6300
  lines w10: 4723,-5054 4755,-5056 4786,-5074 4887,-5165 4900,-5161 4907,-5162 5021,-5249 ; 4778,-5072 4881,-5169 ; 4886,-5172 4901,-5168 5016,-5256 ; 5003,-5272 5049,-5245 5108,-5191 5111,-5184 5111,-5174 5109,-5171 5103,-5170 5096,-5170 ; 5034,-5270 5081,-5307 ; 5038,-5263 5086,-5301 5238,-5163 5247,-5159 5261,-5164 5340,-5078 5343,-5083 5372,-5057 5392,-5053 ; 5110,-5185 5110,-5177 5108,-5173 5103,-5171 5096,-5170 ; 5244,-5167 5259,-5172 ; 5266,-5168 5331,-5095 ; 5334,-5098 5340,-5089 ; 5096,-5170 5022,-5208 5014,-5210 5007,-5208 5003,-5201 5004,-5195 5008,-5187 5019,-5179 5114,-5114 5122,-5105 5125,-5098 5123,-5093 5121,-5089 5117,-5087 5110,-5087 5100,-5090 4972,-5160 4962,-5161 4954,-5156 4949,-5152 4946,-5145 4947,-5139 4951,-5131 4973,-5106 5001,-5079 5040,-5045 5083,-5017 5122,-4999 5171,-4991 5128,-5030 5145,-5030 5174,-5025 5179,-5021 5162,-5031 5146,-5036 5130,-5042 5107,-5047 5072,-5047 5065,-5058 5052,-5066 5037,-5073 5019,-5083 4997,-5113 4979,-5128 4968,-5143 4972,-5147 5002,-5137 5050,-5109 5086,-5089 5110,-5083 5116,-5085 5120,-5096 5109,-5112 5041,-5159 5003,-5191 5002,-5203 5006,-5208 5029,-5204 5046,-5193 5089,-5173 5096,-5170 ; 5087,-5312 5246,-5167 5087,-5312
  text "7" at 9369.21,4336.58 h70
  text "1" at -4980.79,4326.58 h70
  text "2" at -2700.79,4326.58 h70
  text "3" at -340.79,4326.58 h70
  text "4" at 2009.21,4326.58 h70
  text "5" at 4469.21,4326.58 h70
  text "6" at 6839.21,4326.58 h70 r350.54
  text "B" at 10350,4110 h70
  text "B" at -6240,3930 h70
  text "C" at -6220,2360 h70
  text "C" at 10370,2360 h70
  text "D" at -6240,-90 h70
  text "D" at 10350,-90 h70
  text "E" at -6220,-2600 h70
  text "E" at 10370,-2600 h70
  text "M  B  A  R  I" at 4720,-5000 h55
  text "ENGINEER:" at 5840,-5000 h45
  text "TITLE:" at 7340,-5000 h45
  text "Mark Sibenac" at 6350,-5030 h70
  text "F" at -6240,-5050 h70
  text "F" at 10350,-5050 h70
  text "Main Power Distribution" at 7690,-5120 h90
  text "1 831 775 2028" at 6340,-5170 h60
  text "PCB DESIGNER:" at 5840,-5295 h45
  text "Mark Sibenac" at 6350,-5330 h70
  text "MVC - Mapping AUV" at 7710,-5340 h90
  text "Copyright      2003" at 4570,-5350 h60
  text "Monterey Bay Aquarium Research Institute" at 4440,-5460 h45
  text "1 831 775 2028" at 6340,-5470 h60
  text "DATE:" at 5840,-5600 h45
  text "PART NO.:" at 7340,-5600 h45
  text "REV:" at 9440,-5600 h45
  text ".PRINT_DATE" at 5890,-5720 h70
  text "2" at 9720,-5720 h90
  text "MVCPOWR2" at 7700,-5730 h60
  text "M.B.A.R.I." at 4470,-5740 h100
  text "7700 Sandholdt Rd." at 4460,-5840 h60
  text "FILE NAME:" at 5840,-5900 h45
  text "DWG NO:" at 7340,-5900 h45
  text "GERBER:" at 9440,-5900 h45
  text "Moss Landing, CA 95039" at 4460,-5950 h60
  text "1002131-PCB" at 7700,-5990 h60
  text ".PCB_FILE_NAME_NO_PATH" at 5890,-6020 h70
  text ".GM16" at 9550,-6030 h70
  text "Fax: 1 831 775 1646" at 4460,-6050 h60
  text "7" at 9370,-6230 h70
  text "1" at -4980,-6240 h70
  text "2" at -2700,-6240 h70
  text "3" at -340,-6240 h70
  text "4" at 2010,-6240 h70
  text "5" at 4470,-6240 h70
  text "6" at 6840,-6240 h70
Drill Drawing:
  text ".LEGEND" at 4565,-4630 h60
  text "Drill Drawing." at 4545,-4720 h60
  text ".GD1" at 9945,-6040 h90

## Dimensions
3990,-3890 to 3700,-3700 on Mechanical 4
-3890,-4130 to -3700,-3790 on Mechanical 4
3890,-3890 to 3890,3890 on Mechanical 4
-3890,-3890 to 3890,-3890 on Mechanical 4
